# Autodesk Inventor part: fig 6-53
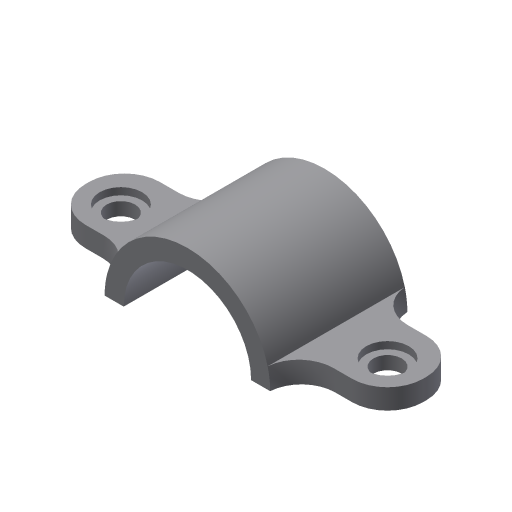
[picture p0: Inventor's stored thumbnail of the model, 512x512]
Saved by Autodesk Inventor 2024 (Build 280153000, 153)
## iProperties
Created: 2004-05
Part Number: fig 6-53
Document SubType Name: Modeling
Designer: CADCIM Technologies
Manufacturer: Standard
Standards Organization: Custom
Density: 1 g/cm^3
Material: Generic
Appearance: Default
Author: CADCIM Technologies
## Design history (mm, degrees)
sketch "Sketch2"
  geometry: L1 (23.378, 0)-(17.996, 0); L2 (-17.996, 0)-(-23.378, 0); A1 r 23.378 centre (0, 0) between (23.378, 0) and (-23.378, 0); A2 r 17.996 centre (0, 0) between (17.996, 0) and (-17.996, 0)
  constraints: 4 end point, 4 point on circle, 2 centre point, 1 collinear, 1 horizontal
extrude "Extrusion1" new body sketch "Sketch2" stored distance "d0" = 38.75; taper "d1" = 0 deg
sketch "Sketch3"
  geometry: L1 (23.378, 0)-(17.996, 0); L2 (-17.996, 0)-(-23.378, 0) reference; L3 (-23.378, 0)-(-47.662, 0); L4 (-47.662, 0)-(-47.662, 5.722); L5 (-47.662, 5.722)-(-22.667, 5.722); A1 r 17.996 centre (0, 0) between (17.996, 0) and (-17.996, 0) reference; A2 r 23.378 centre (0, 0) between (23.378, 0) and (-23.378, 0) reference; 1 further point
  constraints: 10 end point, 5 point on circle, 2 centre point, 1 collinear, 1 horizontal, 1 midpoint, 1 parallel, 1 perpendicular, 3 other
extrude "Extrusion2" join sketch "Sketch3" stored distance "d2" = 21; taper "d3" = 0 deg
fillet "Fillet1" dims "d4" = 10
hole "Hole1" diameter "d7" = 8; stored, may be unused: countersink angle "d11" = 90 deg, drill point angle "d13" = 118 deg; dims "d5" = 10, "d6" = 10, "d8" = 6, "d9" = 12, "d10" = 2, "d12" = 12
fillet "Fillet2" dims "d14" = 9.5
mirror "Mirror1"
body "Solid1"
node "Sketch1"
